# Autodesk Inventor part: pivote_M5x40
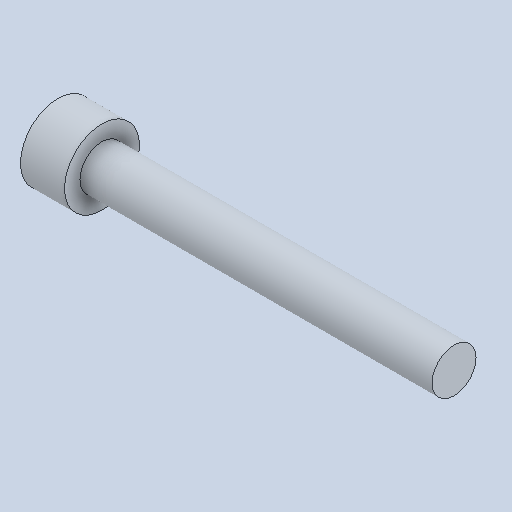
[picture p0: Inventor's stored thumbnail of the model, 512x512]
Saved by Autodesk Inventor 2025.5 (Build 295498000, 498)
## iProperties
Created: 2026-10
Part Number: pivote_M5x40
Material: Genérico
Document SubType Name: Modeling
Designer: Luis M
Density: 1 g/cm^3
Appearance: Valor por defecto
Author: Luis M
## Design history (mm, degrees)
feature "Base1"
node "Sólido1"
